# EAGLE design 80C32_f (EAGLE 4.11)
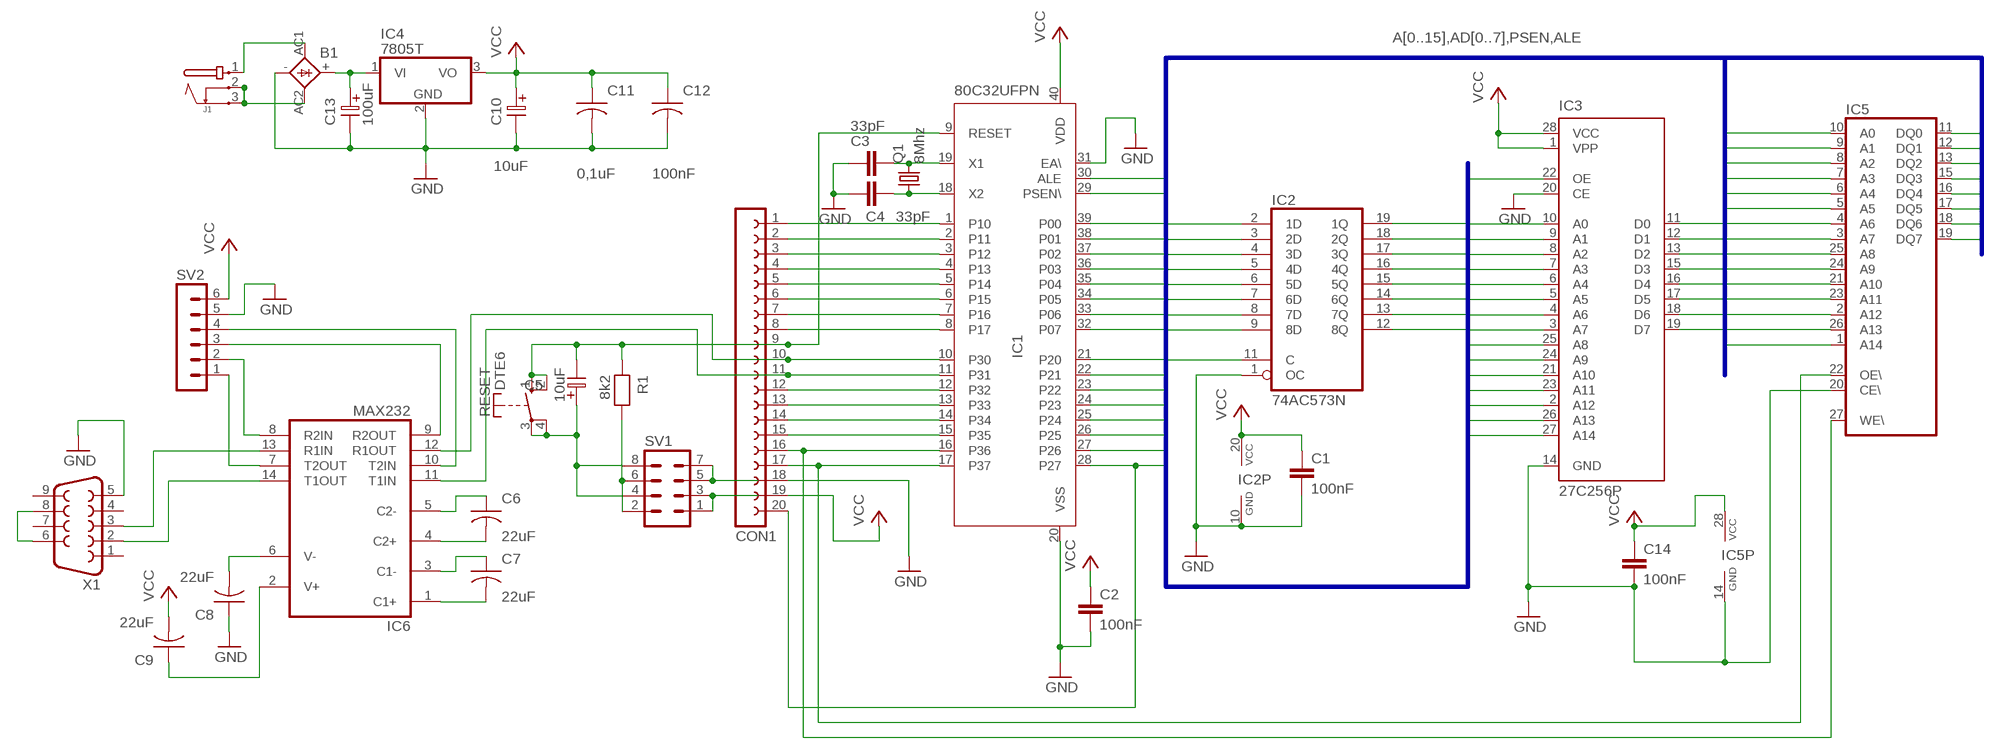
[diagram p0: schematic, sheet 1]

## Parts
B1  1KAB  [1KAB]
C1  100nF  C2,5-3  [C2.5-3]
C2  100nF  C2,5-3  [C2.5-3]
C3  33pF  C2,5-3  [C2.5-3]
C4  33pF  C2,5-3  [C2.5-3]
C5  10uF  ELC-5  [ES-5]
C6  22uF  CAP-2,5  [C-2,5]
C7  22uF  CAP-2,5  [C-2,5]
C8  22uF  CAP-2,5  [C-2,5]
C9  22uF  CAP-2,5  [C-2,5]
C10  10uF  ELC-5  [ES-5]
C11  0,1uF  CAP-5  [C-5]
C12  100nF  CAP-5  [C-5]
C13  100uF  ELC-5  [ES-5]
C14  100nF  C2,5-3  [C2.5-3]
CON1  FE20-1  [FE20]
IC1  80C32UFPN  [DIL40]
IC2  74AC573N  [DIL20]
IC3  27C256P  [DIL28-6]
IC4  7805T  [TO220H]
IC5  KM68257DIL28-3  [DIL28-3]
IC6  MAX232  [DIL16]
J1  JACK-PMS  [JACK-PMS]
Q1  8Mhz  HC49/S  [HC49/S]
R1  8k2  RESEU-5  [R-5]
RESET  DTE6  [DTE6]
SV1  MA04-2  [MA04-2]
SV2  MA06-1  [MA06-1]
X1  F09H  [F09H]

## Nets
A0: IC2.12(8Q) IC3.10(A0) IC5.10(A0)
A1: IC2.13(7Q) IC3.9(A1) IC5.9(A1)
A2: IC2.14(6Q) IC3.8(A2) IC5.8(A2)
A3: IC2.15(5Q) IC3.7(A3) IC5.7(A3)
A4: IC2.16(4Q) IC3.6(A4) IC5.6(A4)
A5: IC2.17(3Q) IC3.5(A5) IC5.5(A5)
A6: IC2.18(2Q) IC3.4(A6) IC5.4(A6)
A7: IC2.19(1Q) IC3.3(A7) IC5.3(A7)
A8: IC1.21(P20) IC3.25(A8) IC5.25(A8)
A9: IC1.22(P21) IC3.24(A9) IC5.24(A9)
A10: IC1.23(P22) IC3.21(A10) IC5.21(A10)
A11: IC1.24(P23) IC3.23(A11) IC5.23(A11)
A12: IC1.25(P24) IC3.2(A12) IC5.2(A12)
A13: IC1.26(P25) IC3.26(A13) IC5.26(A13)
A14: IC1.27(P26) IC3.27(A14) IC5.1(A14)
A15: CON1.20 IC1.28(P27)
AD0: IC1.39(P00) IC2.9(8D) IC3.11(D0) IC5.11(DQ0)
AD1: IC1.38(P01) IC2.8(7D) IC3.12(D1) IC5.12(DQ1)
AD2: IC1.37(P02) IC2.7(6D) IC3.13(D2) IC5.13(DQ2)
AD3: IC1.36(P03) IC2.6(5D) IC3.15(D3) IC5.15(DQ3)
AD4: IC1.35(P04) IC2.5(4D) IC3.16(D4) IC5.16(DQ4)
AD5: IC1.34(P05) IC2.4(3D) IC3.17(D5) IC5.17(DQ5)
AD6: IC1.33(P06) IC2.3(2D) IC3.18(D6) IC5.18(DQ6)
AD7: IC1.32(P07) IC2.2(1D) IC3.19(D7) IC5.19(DQ7)
ALE: IC1.30(ALE) IC2.11(C)
GND: B1.- C1.2 C2.2 C3.1 C4.1 C8.1 C10.2 C11.2 C12.2 C13.2 C14.2 CON1.18 IC1.20(VSS) IC1.31(EA\) IC2.1(OC) IC2.10(GND) IC3.14(GND) IC3.20(CE) IC4.2(GND) IC5.14(GND) IC5.20(CE\) SV1.5 SV1.7 SV2.5 X1.5
N$1: CON1.17 IC1.17(P37) IC5.22(OE\)
N$2: CON1.16 IC1.16(P36) IC5.27(WE\)
N$3: CON1.15 IC1.15(P35)
N$4: CON1.14 IC1.14(P34)
N$5: CON1.13 IC1.13(P33)
N$6: CON1.12 IC1.12(P32)
N$7: CON1.11 IC1.11(P31) IC6.11(T1IN)
N$8: CON1.10 IC1.10(P30) IC6.12(R1OUT)
N$9: CON1.8 IC1.8(P17)
N$10: CON1.7 IC1.7(P16)
N$11: CON1.6 IC1.6(P15)
N$12: CON1.5 IC1.5(P14)
N$13: CON1.4 IC1.4(P13)
N$14: CON1.3 IC1.3(P12)
N$15: CON1.2 IC1.2(P11)
N$16: CON1.1 IC1.1(P10)
N$17: C5.2 CON1.9 IC1.9(RESET) R1.1 RESET.1(S) RESET.2(S)
N$18: C4.2 IC1.18(X2) Q1.1
N$19: C3.2 IC1.19(X1) Q1.2
N$20: X1.6 X1.8
N$21: IC6.13(R1IN) X1.3
N$22: IC6.14(T1OUT) X1.2
N$23: IC6.7(T2OUT) SV2.1
N$24: IC6.8(R2IN) SV2.2
N$25: C9.1 IC6.2(V+)
N$26: C6.2 IC6.4(C2+)
N$27: C7.2 IC6.1(C1+)
N$28: C7.1 IC6.3(C1-)
N$29: C6.1 IC6.5(C2-)
N$30: C8.2 IC6.6(V-)
N$31: IC6.10(T2IN) SV2.4
N$32: IC6.9(R2OUT) SV2.3
N$33: B1.AC2 J1.2 J1.3
N$34: B1.AC1 J1.1
N$35: R1.2 SV1.2 SV1.6
N$36: B1.+ C13.1 IC4.1(VI)
N$37: C5.1 RESET.3(P) RESET.4(P) SV1.4 SV1.8
PSEN\: IC1.29(PSEN\) IC3.22(OE)
VCC: C1.1 C2.1 C9.2 C10.1 C11.1 C12.1 C14.1 CON1.19 IC1.40(VDD) IC2.20(VCC) IC3.1(VPP) IC3.28(VCC) IC4.3(VO) IC5.28(VCC) SV1.1 SV1.3 SV2.6
Unconnected: X1.1 X1.4 X1.7 X1.9

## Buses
A[0..15],AD[0..7],PSEN\,ALE

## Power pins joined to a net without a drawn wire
GND: IC6.15(GND)
VCC: IC6.16(VCC)

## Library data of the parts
B1 = rectifier:1KAB: RECTIFIER grid 5,08 x 5,08 mm
C1-C4 C14 = capacitor-wima:C: CAPACITOR
C5 C10 C13 = discrete:ELC-5
C6-C9 = discrete:CAP-2,5
C11 C12 = discrete:CAP-5
CON1 = con-lsta:FE20-1: FEMALE HEADER
IC1 = micro-philips:8*: CMOS single-chip 8-bit Microcontroller 80C31/32 pin compatible
IC2 = 74xx-eu:74*573: 8-bit D latch BUS DRIVER
IC3 = microchip:27*256: CMOS EPROM 256 K (32 K x 8), low voltage
IC4 = linear:78*: Positive VOLTAGE REGULATOR
IC5 = memory-samsung:KM68257: MEMORY
IC6 = maxim:MAX232: RS232 TRANSEIVER
J1 = POWER-IN:JACK-PMS
Q1 = Crystal3:HC49/S: CRYSTAL
R1 = discrete:RESEU-5
RESET = switch-misc:DT: ITT SWITCH
SV1 = con-lstb:MA04-2: PIN HEADER
SV2 = con-lstb:MA06-1: PIN HEADER
X1 = con-subd:F09: HARTING SUB-D

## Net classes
1 Supply: width 1.016 mm, drill 24 mm, clearance 0.61 mm

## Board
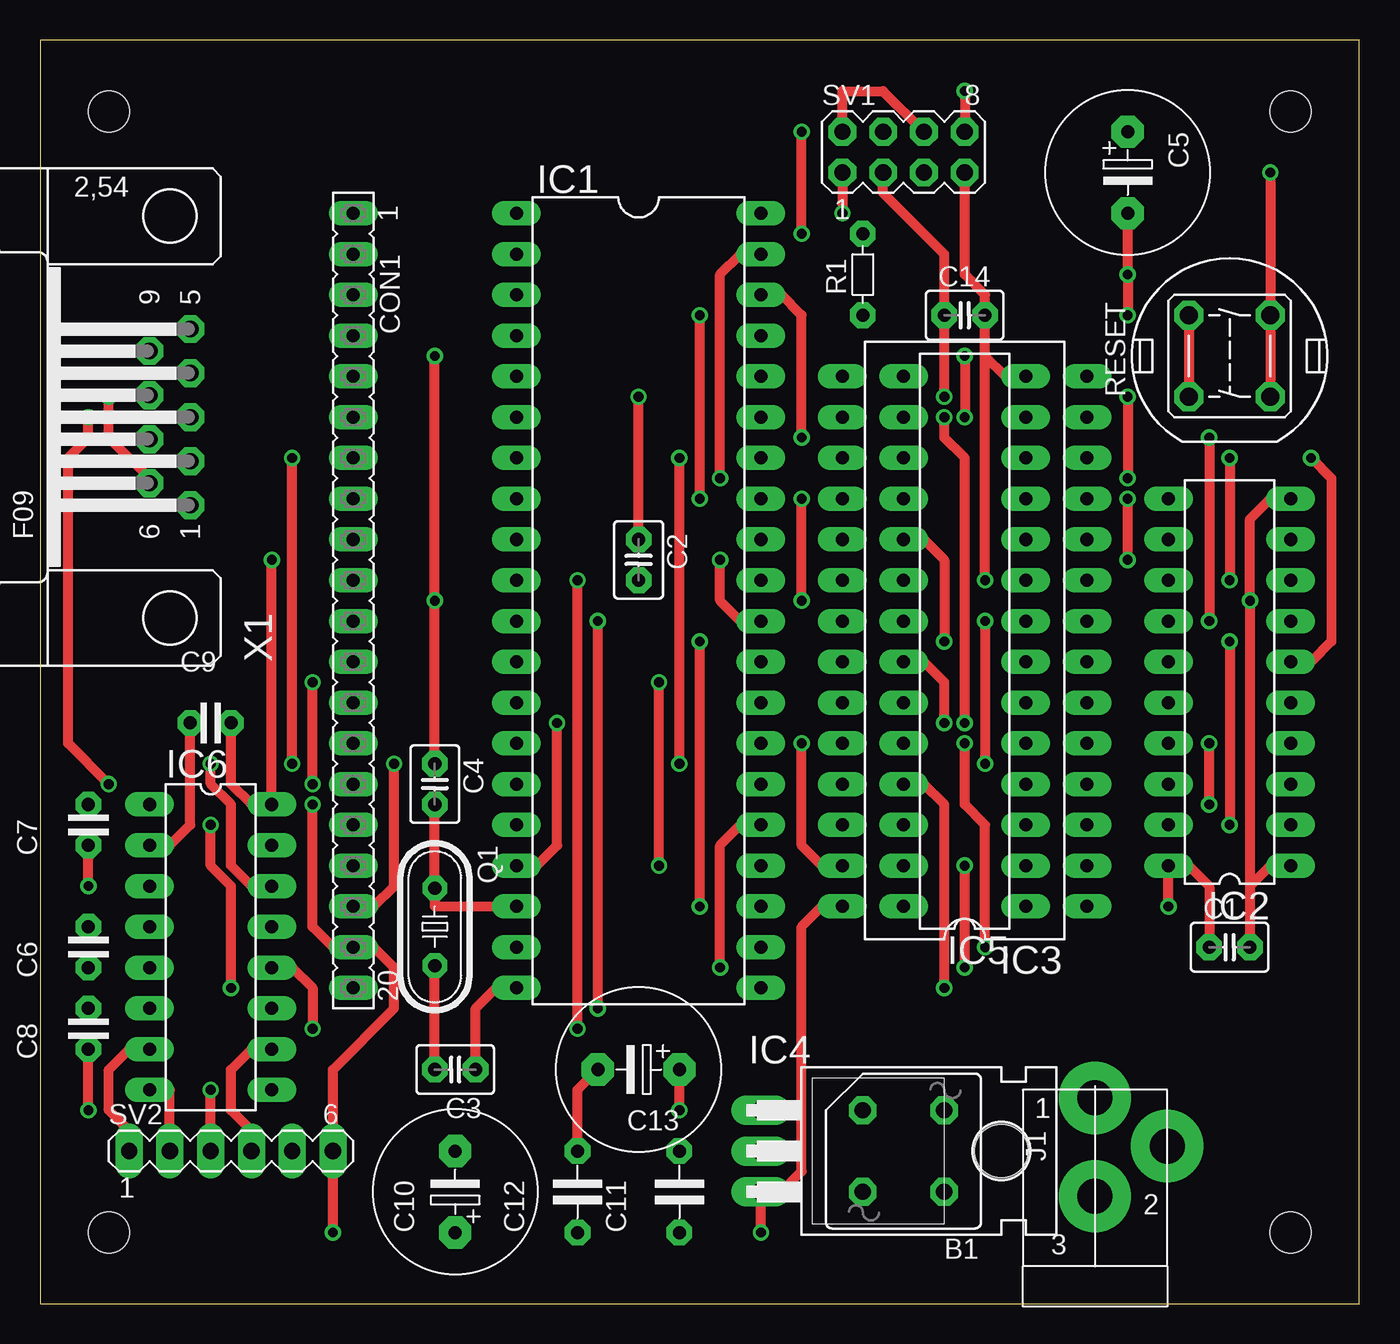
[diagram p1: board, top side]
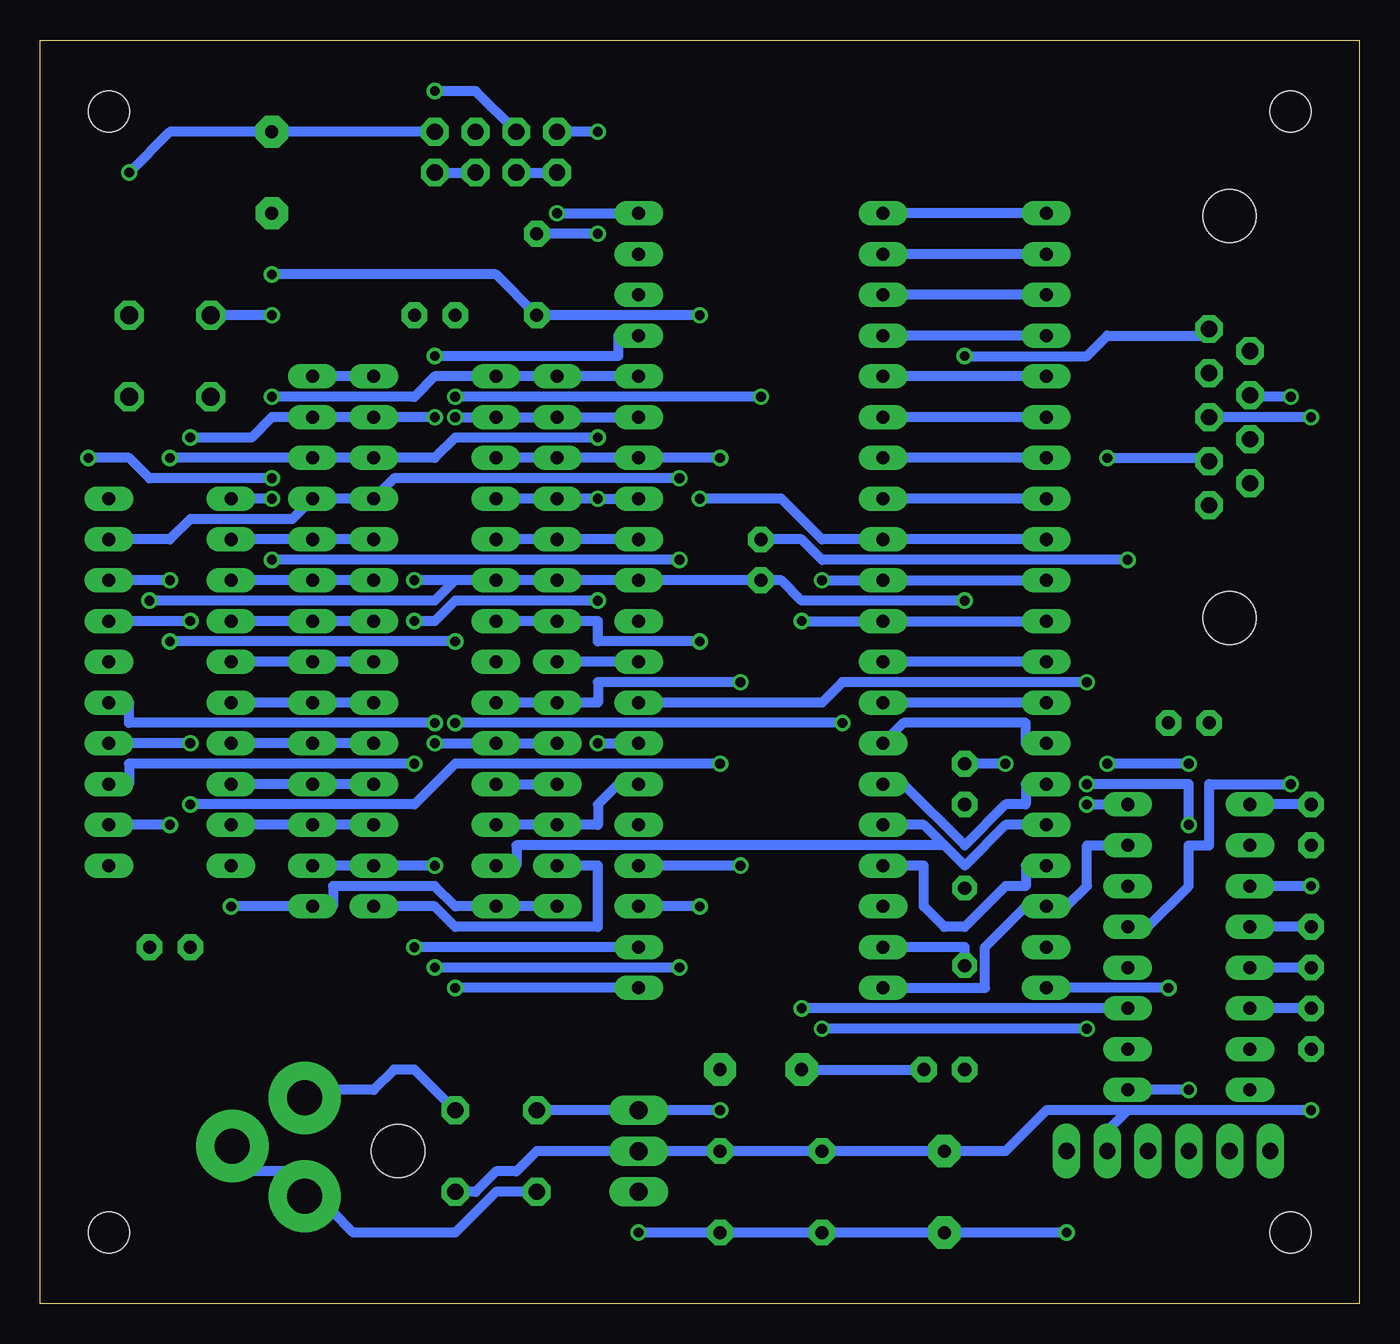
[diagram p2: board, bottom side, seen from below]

Size 82.22 x 78.73 mm. Coordinates in mm from the lower left corner, seen from the top.
Outline: 0,0 82.22,0 82.22,78.73 0,78.73 0,0
Copper layers (1*16): Top 0.035mm / dielectric 1.5mm / Bottom 0.035mm
Design rules "default": minimum track width 24mil, minimum drill 24mil, track to track 8mil, track to pad 8mil, pad to pad 8mil, via to via 8mil, smd to smd 8mil, copper to edge 40mil, drill to drill 8mil, minimum pad ring 14mil, minimum via ring 8mil, stop-mask expansion 4mil, vias tented up to drill 0mil, thermal gap 10mil
Holes 2.54 mm at 4.28,74.29 77.94,74.29 77.94,4.44 4.28,4.44

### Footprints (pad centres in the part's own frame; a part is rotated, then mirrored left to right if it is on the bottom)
1KAB = drill 1.016 octagon: + 2.54,-2.54; - -2.54,2.54; AC1 -2.54,-2.54; AC2 2.54,2.54
C2.5-3 = drill 0.813 pad 1.6 octagon: 1 -1.27,0; 2 1.27,0
ES-5 = drill 0.813 pad 2.007 octagon: 1 -2.54,0; 2 2.54,0
C-2,5 = drill 0.813 pad 1.6 octagon: 1 -1.27,0; 2 1.27,0
C-5 = drill 0.813 pad 1.6 octagon: 1 -2.54,0; 2 2.54,0
FE20 = drill 0.813 long: 1 -24.13,0; 2 -21.59,0; 3 -19.05,0; 4 -16.51,0; 5 -13.97,0; 6 -11.43,0; 7 -8.89,0; 8 -6.35,0; 9 -3.81,0; 10 -1.27,0; 11 1.27,0; 12 3.81,0; 13 6.35,0; 14 8.89,0; 15 11.43,0; 16 13.97,0; 17 16.51,0; 18 19.05,0; 19 21.59,0; 20 24.13,0
DIL40 = drill 0.813 long: 1 -24.13,-7.62; 2 -21.59,-7.62; 3 -19.05,-7.62; 4 -16.51,-7.62; 5 -13.97,-7.62; 6 -11.43,-7.62; 7 -8.89,-7.62; 8 -6.35,-7.62; 9 -3.81,-7.62; 10 -1.27,-7.62; 11 1.27,-7.62; 12 3.81,-7.62; 13 6.35,-7.62; 14 8.89,-7.62; 15 11.43,-7.62; 16 13.97,-7.62; 17 16.51,-7.62; 18 19.05,-7.62; 19 21.59,-7.62; 20 24.13,-7.62; 21 24.13,7.62; 22 21.59,7.62; 23 19.05,7.62; 24 16.51,7.62; 25 13.97,7.62; 26 11.43,7.62; 27 8.89,7.62; 28 6.35,7.62; 29 3.81,7.62; 30 1.27,7.62; 31 -1.27,7.62; 32 -3.81,7.62; 33 -6.35,7.62; 34 -8.89,7.62; 35 -11.43,7.62; 36 -13.97,7.62; 37 -16.51,7.62; 38 -19.05,7.62; 39 -21.59,7.62; 40 -24.13,7.62
DIL20 = drill 0.813 long: 1 -11.43,-3.81; 2 -8.89,-3.81; 3 -6.35,-3.81; 4 -3.81,-3.81; 5 -1.27,-3.81; 6 1.27,-3.81; 7 3.81,-3.81; 8 6.35,-3.81; 9 8.89,-3.81; 10 11.43,-3.81; 11 11.43,3.81; 12 8.89,3.81; 13 6.35,3.81; 14 3.81,3.81; 15 1.27,3.81; 16 -1.27,3.81; 17 -3.81,3.81; 18 -6.35,3.81; 19 -8.89,3.81; 20 -11.43,3.81
DIL28-6 = drill 0.813 long: 1 -16.51,-7.62; 2 -13.97,-7.62; 3 -11.43,-7.62; 4 -8.89,-7.62; 5 -6.35,-7.62; 6 -3.81,-7.62; 7 -1.27,-7.62; 8 1.27,-7.62; 9 3.81,-7.62; 10 6.35,-7.62; 11 8.89,-7.62; 12 11.43,-7.62; 13 13.97,-7.62; 14 16.51,-7.62; 15 16.51,7.62; 16 13.97,7.62; 17 11.43,7.62; 18 8.89,7.62; 19 6.35,7.62; 20 3.81,7.62; 21 1.27,7.62; 22 -1.27,7.62; 23 -3.81,7.62; 24 -6.35,7.62; 25 -8.89,7.62; 26 -11.43,7.62; 27 -13.97,7.62; 28 -16.51,7.62
TO220H = drill 1.118 long: 1 -2.54,-10.16; 2 0,-10.16; 3 2.54,-10.16 | hole 3.302: 0,4.826
DIL28-3 = drill 0.813 long: 1 -16.51,-3.81; 2 -13.97,-3.81; 3 -11.43,-3.81; 4 -8.89,-3.81; 5 -6.35,-3.81; 6 -3.81,-3.81; 7 -1.27,-3.81; 8 1.27,-3.81; 9 3.81,-3.81; 10 6.35,-3.81; 11 8.89,-3.81; 12 11.43,-3.81; 13 13.97,-3.81; 14 16.51,-3.81; 15 16.51,3.81; 16 13.97,3.81; 17 11.43,3.81; 18 8.89,3.81; 19 6.35,3.81; 20 3.81,3.81; 21 1.27,3.81; 22 -1.27,3.81; 23 -3.81,3.81; 24 -6.35,3.81; 25 -8.89,3.81; 26 -11.43,3.81; 27 -13.97,3.81; 28 -16.51,3.81
DIL16 = drill 0.813 long: 1 -8.89,-3.81; 2 -6.35,-3.81; 3 -3.81,-3.81; 4 -1.27,-3.81; 5 1.27,-3.81; 6 3.81,-3.81; 7 6.35,-3.81; 8 8.89,-3.81; 9 8.89,3.81; 10 6.35,3.81; 11 3.81,3.81; 12 1.27,3.81; 13 -1.27,3.81; 14 -3.81,3.81; 15 -6.35,3.81; 16 -8.89,3.81
JACK-PMS = drill 2.184 pad 4.5 round: 1 -0.5,-3.31; 2 -5,-0.31; 3 -0.5,2.809
HC49/S = drill 0.813 octagon: 1 -2.413,0; 2 2.413,0
R-5 = drill 0.813 pad 1.6 octagon: 1 -2.54,0; 2 2.54,0
DTE6 = drill 1.118 octagon: 1 -2.54,2.54; 2 2.54,2.54; 3 2.54,-2.54; 4 -2.54,-2.54
MA04-2 = drill 1.016 octagon: 1 -3.81,-1.27; 2 -3.81,1.27; 3 -1.27,-1.27; 4 -1.27,1.27; 5 1.27,-1.27; 6 1.27,1.27; 7 3.81,-1.27; 8 3.81,1.27
MA06-1 = drill 1.016 long: 1 -6.35,0; 2 -3.81,0; 3 -1.27,0; 4 1.27,0; 5 3.81,0; 6 6.35,0
F09H = drill 1.016 octagon: 1 -5.486,-1.27; 2 -2.743,-1.27; 3 0,-1.27; 4 2.743,-1.27; 5 5.486,-1.27; 6 -4.115,1.27; 7 -1.372,1.27; 8 1.372,1.27; 9 4.115,1.27 | hole 3.302: -12.522,0; 12.522,0

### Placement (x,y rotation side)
B1  53.81,9.52 180 top
C1  74.13,22.22 0 top
C2  37.3,46.35 270 top
C3  25.87,14.6 180 top
C4  24.6,32.38 270 top
C5  67.78,70.48 270 top
C6  3.01,22.22 90 top
C7  3.01,29.84 90 top
C8  3.01,17.14 90 top
C9  10.63,36.19 0 top
C10  25.87,6.98 90 top
C11  39.84,6.98 90 top
C12  33.49,6.98 90 top
C13  37.3,14.6 180 top
C14  57.62,61.59 0 top
CON1  19.52,43.81 270 top
IC1  37.3,43.81 270 top
IC2  74.13,38.73 90 top
IC3  57.62,41.27 90 top
IC4  55.08,9.52 270 top
IC5  57.62,41.27 90 top
IC6  10.63,22.22 270 top
J1  65.24,9.52 180 top
Q1  24.6,23.49 270 top
R1  51.27,64.13 90 top
RESET  74.13,59.05 90 top
SV1  53.81,71.75 0 top
SV2  11.9,9.52 0 top
X1  8.09,55.24 90 top

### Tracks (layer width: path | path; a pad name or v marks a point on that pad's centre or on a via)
A0
  Bottom 0.61: IC5.10 IC3.10 IC2.12
A1
  Bottom 0.61: IC5.9 IC3.9 IC2.13
A2
  Bottom 0.61: IC5.8 IC3.8 IC2.14
A3
  Bottom 0.61: IC5.7 IC3.7 IC2.15
A4
  Bottom 0.61: IC5.6 IC3.6 IC2.16
A5
  Bottom 0.61: IC5.5 IC3.5 IC2.17
A6
  Bottom 0.61: IC5.4 IC3.4 IC2.18
A7
  Bottom 0.61: IC5.3 IC3.3 IC2.19
A8  (via drill 0.61)
  Top 0.61: v56.35,19.68 56.35,31.11 55.08,32.38 IC5.25
  Bottom 0.61: IC1.21 v56.35,19.68 | IC5.25 IC3.25
A9  (via drill 0.61)
  Top 0.61: v58.89,22.22 58.89,29.84 57.62,31.11 v57.62,34.92
  Bottom 0.61: IC1.22 v58.89,22.22 | v57.62,34.92 IC5.24 IC3.24
A10  (via drill 0.61)
  Top 0.61: v41.11,24.76 v41.11,41.27
  Bottom 0.61: v41.11,41.27 47.46,41.27 47.46,42.54 IC3.21 IC5.21 | v41.11,24.76 IC1.23
A11  (via drill 0.61)
  Top 0.61: v38.57,27.3 v38.57,38.73
  Bottom 0.61: v38.57,38.73 47.46,38.73 47.46,37.46 IC3.23 IC5.23 | v38.57,27.3 IC1.24
A12  (via drill 0.61)
  Top 0.61: v42.38,20.95 42.38,28.57 43.65,29.84 IC1.25 | v57.62,20.95 v57.62,27.3
  Bottom 0.61: IC3.2 IC5.2 v57.62,27.3 | v42.38,20.95 v57.62,20.95
A13
  Bottom 0.61: IC5.26 IC3.26 47.46,29.84 47.46,31.11 46.19,32.38 IC1.26
A14  (via drill 0.61)
  Top 0.61: v47.46,34.92 47.46,28.57 48.73,27.3 IC3.27
  Bottom 0.61: v47.46,34.92 IC1.27 | IC5.1 57.62,24.76 56.35,23.49 47.46,23.49 47.46,27.3 IC3.27
A15  (via drill 0.61)
  Top 0.61: v11.9,19.68 11.9,26.03 10.63,27.3 v10.63,29.84 | v16.98,32.38 v16.98,38.73
  Bottom 0.61: v10.63,29.84 10.63,32.38 v16.98,32.38 | v16.98,38.73 32.22,38.73 33.49,37.46 IC1.28 | v11.9,19.68 CON1.20
AD0  (via drill 0.61)
  Top 0.61: v42.38,51.43 42.38,64.13 43.65,65.4 IC1.39
  Bottom 0.61: v42.38,51.43 60.16,51.43 IC5.11 IC3.11 66.51,48.89 72.86,48.89 74.13,47.62 IC2.9
AD1  (via drill 0.61)
  Top 0.61: v47.46,53.97 47.46,61.59 46.19,62.86 IC1.38 | v74.13,52.7 v74.13,45.08
  Bottom 0.61: v47.46,53.97 56.35,53.97 57.62,52.7 IC5.12 IC3.12 v74.13,52.7 | v74.13,45.08 IC2.8
AD2  (via drill 0.61)
  Top 0.61: v57.62,59.05 v57.62,55.24 | v72.86,53.97 v72.86,42.54
  Bottom 0.61: v57.62,59.05 46.19,59.05 46.19,60.32 IC1.37 | v57.62,55.24 IC5.13 IC3.13 67.78,55.24 69.05,53.97 v72.86,53.97 | v72.86,42.54 IC2.7
AD3  (via drill 0.61)
  Top 0.61: v79.21,52.7 80.48,51.43 80.48,41.27 79.21,40 IC2.6 | v67.78,56.51 v67.78,51.43
  Bottom 0.61: IC1.36 IC3.15 IC5.15 57.62,57.78 58.89,56.51 v67.78,56.51 | v79.21,52.7 76.67,52.7 75.4,51.43 v67.78,51.43
AD4  (via drill 0.61)
  Top 0.61: v57.62,36.19 57.62,52.7 56.35,53.97 v56.35,55.24
  Bottom 0.61: IC1.35 IC3.16 IC5.16 v56.35,55.24 | v57.62,36.19 76.67,36.19 76.67,37.46 IC2.5
AD5  (via drill 0.61)
  Top 0.61: v72.86,31.11 v72.86,34.92 | v39.84,33.65 v39.84,52.7
  Bottom 0.61: IC5.17 IC3.17 IC1.34 v39.84,52.7 | v72.86,31.11 58.89,31.11 56.35,33.65 v39.84,33.65 | v72.86,34.92 IC2.4
AD6  (via drill 0.61)
  Top 0.61: v58.89,42.54 v58.89,33.65 | v47.46,43.81 v47.46,50.16
  Bottom 0.61: IC1.33 v47.46,50.16 IC3.18 IC5.18 | v58.89,33.65 76.67,33.65 76.67,32.38 IC2.3 | v58.89,42.54 57.62,42.54 56.35,43.81 v47.46,43.81
AD7  (via drill 0.61)
  Top 0.61: v74.13,41.27 v74.13,29.84 | v56.35,41.27 56.35,46.35 55.08,47.62 IC5.19
  Bottom 0.61: IC1.32 IC3.19 IC5.19 | v56.35,41.27 v74.13,41.27 | v74.13,29.84 IC2.2
ALE  (via drill 0.61)
  Top 0.61: v42.38,46.35 42.38,43.81 43.65,42.54 IC1.30 | v67.78,46.35 v67.78,50.16
  Bottom 0.61: v42.38,46.35 v67.78,46.35 | v67.78,50.16 IC2.11
GND  (via drill 0.61)
  Top 0.61: C3.1 27.14,18.41 28.41,19.68 IC1.20 | v3.01,12.06 C8.1 | C13.2 33.49,13.33 C12.2 | 75.4,26.03 76.67,27.3 IC2.1 | 75.4,26.03 C1.2 | 75.4,26.03 v75.4,43.81 75.4,48.89 76.67,50.16 IC2.10 | 58.89,59.05 C14.2 58.89,62.86 57.62,64.13 SV1.7 | 58.89,59.05 60.16,57.78 IC5.14 | C4.1 v24.6,43.81 v24.6,59.05 | v58.89,45.08 58.89,59.05 | v22.06,33.65 22.06,26.03 20.79,24.76 CON1.18
  Bottom 0.61: IC6.15 16.98,28.57 16.98,26.03 18.25,24.76 CON1.18 20.79,24.76 23.33,22.22 23.33,19.68 IC1.20 | C13.2 C3.1 | v3.01,12.06 14.44,12.06 | 14.44,12.06 15.71,10.79 SV2.5 | B1.- 55.08,6.98 53.81,8.25 52.54,8.25 51.27,9.52 IC4.2 C11.2 C12.2 C10.2 22.06,9.52 19.52,12.06 14.44,12.06 | SV1.7 SV1.5 | IC5.14 IC3.14 | v24.6,43.81 34.76,43.81 36.03,45.08 C2.2 IC1.31 IC3.20 IC5.20 56.35,45.08 | v24.6,59.05 16.98,59.05 15.71,60.32 9.36,60.32 X1.5 | 56.35,45.08 v58.89,45.08 | v75.4,43.81 57.62,43.81 56.35,45.08 | v22.06,33.65 C4.1
N$1  (via drill 0.61)
  Top 0.61: v56.35,36.19 56.35,38.73 55.08,40 IC5.22 | v32.22,36.19 32.22,28.57 30.95,27.3 IC1.17
  Bottom 0.61: CON1.17 20.79,27.3 20.79,26.03 22.06,26.03 24.6,23.49 25.87,23.49 27.14,24.76 27.14,27.3 IC1.17 | v32.22,36.19 v56.35,36.19
N$2
  Bottom 0.61: 25.87,28.57 27.14,29.84 IC1.16 | 25.87,28.57 24.6,27.3 22.06,29.84 CON1.16 | 25.87,28.57 52.54,28.57 52.54,27.3 IC5.27
N$3
  Bottom 0.61: CON1.15 20.79,32.38 20.79,31.11 22.06,31.11 24.6,28.57 28.41,32.38 IC1.15
N$4
  Bottom 0.61: IC1.14 28.41,36.19 20.79,36.19 20.79,34.92 CON1.14
N$5
  Bottom 0.61: CON1.13 IC1.13
N$6
  Bottom 0.61: CON1.12 IC1.12
N$7  (via drill 0.61)
  Top 0.61: v34.76,18.41 v34.76,42.54
  Bottom 0.61: IC6.11 v34.76,18.41 | v34.76,42.54 IC1.11 CON1.11
N$8  (via drill 0.61)
  Top 0.61: v16.98,17.14 16.98,19.68 15.71,20.95 IC6.12 | v33.49,17.14 v33.49,45.08
  Bottom 0.61: v16.98,17.14 v33.49,17.14 | v33.49,45.08 IC1.10 CON1.10
N$9
  Bottom 0.61: CON1.8 IC1.8
N$10
  Bottom 0.61: CON1.7 IC1.7
N$11
  Bottom 0.61: CON1.6 IC1.6
N$12
  Bottom 0.61: CON1.5 IC1.5
N$13
  Bottom 0.61: CON1.4 IC1.4
N$14
  Bottom 0.61: CON1.3 IC1.3
N$15
  Bottom 0.61: CON1.2 IC1.2
N$16
  Bottom 0.61: CON1.1 IC1.1
N$17  (via drill 0.61)
  Top 0.61: RESET.2 RESET.1 | C5.2 v67.78,64.13 v67.78,61.59 | v41.11,50.16 v41.11,61.59
  Bottom 0.61: CON1.9 IC1.9 33.49,47.62 36.03,50.16 v41.11,50.16 | v67.78,64.13 53.81,64.13 R1.1 v41.11,61.59 | v67.78,61.59 RESET.2
N$18
  Top 0.61: IC1.18 24.6,24.76 Q1.1 24.6,26.03 C4.2
N$19
  Top 0.61: C3.2 Q1.2
  Bottom 0.61: IC1.19 24.6,22.22 Q1.2 24.6,20.95
N$20  (via drill 0.61)
  Top 0.61: v4.28,56.51 4.28,53.97 6.82,51.43 X1.6
  Bottom 0.61: v4.28,56.51 6.82,56.51 X1.8
N$21  (via drill 0.61)
  Top 0.61: v4.28,32.38 1.74,34.92 1.74,52.7 3.01,53.97 v3.01,55.24
  Bottom 0.61: v4.28,32.38 9.36,32.38 9.36,28.57 10.63,28.57 10.63,26.03 13.17,23.49 IC6.13 | v3.01,55.24 X1.3
N$22  (via drill 0.61)
  Top 0.61: v10.63,33.65 10.63,32.38 11.9,31.11 11.9,27.3 13.17,26.03 IC6.14 | v15.71,33.65 v15.71,52.7
  Bottom 0.61: v10.63,33.65 v15.71,33.65 | v15.71,52.7 9.36,52.7 X1.2
N$23
  Top 0.61: IC6.7 5.55,15.87 4.28,14.6 4.28,12.06 5.55,10.79 SV2.1
N$24
  Top 0.61: IC6.8 8.09,13.33 SV2.2
N$25
  Top 0.61: C9.1 9.36,29.84 8.09,28.57 IC6.2
N$26
  Bottom 0.61: C6.2 IC6.4
N$27
  Bottom 0.61: C7.2 IC6.1
N$28  (via drill 0.61)
  Top 0.61: v3.01,26.03 C7.1
  Bottom 0.61: v3.01,26.03 IC6.3
N$29
  Bottom 0.61: C6.1 IC6.5
N$30
  Bottom 0.61: C8.2 IC6.6
N$31
  Top 0.61: IC6.10 13.17,15.87 11.9,14.6 11.9,12.06 13.17,10.79 SV2.4
N$32  (via drill 0.61)
  Top 0.61: SV2.3 v10.63,13.33
  Bottom 0.61: v10.63,13.33 IC6.9
N$33
  Bottom 0.61: B1.AC2 53.81,6.98 56.35,4.44 62.7,4.44 63.97,5.71 J1.3 66.51,8.25 69.05,8.25 J1.2
N$34
  Bottom 0.61: B1.AC1 58.89,14.6 60.16,14.6 61.43,13.33 63.97,13.33 J1.1
N$35  (via drill 0.61)
  Top 0.61: v47.46,66.67 v47.46,73.02 | SV1.6 52.54,75.56 50,75.56 SV1.2
  Bottom 0.61: v47.46,66.67 R1.2 | v47.46,73.02 SV1.2
N$36  (via drill 0.61)
  Top 0.61: v39.84,12.06 C13.1
  Bottom 0.61: B1.+ IC4.1 v39.84,12.06
N$37  (via drill 0.61)
  Top 0.61: RESET.4 RESET.3 v76.67,70.48 | v57.62,75.56 SV1.8
  Bottom 0.61: SV1.4 55.08,75.56 v57.62,75.56 | SV1.8 C5.1 74.13,73.02 v76.67,70.48
PSEN\
  Bottom 0.61: IC1.29 IC3.22
VCC  (via drill 0.61)
  Top 0.61: C1.1 72.86,26.03 71.59,27.3 IC2.20 v70.32,24.76 | v18.25,4.44 SV2.6 18.25,14.6 22.06,18.41 22.06,20.95 20.79,22.22 CON1.19 18.25,22.22 16.98,23.49 v16.98,31.11 | v44.92,4.44 IC4.3 46.19,6.98 47.46,8.25 47.46,23.49 48.73,24.76 IC3.28 | SV1.1 v50,67.94 | SV1.3 52.54,69.21 56.35,65.4 C14.1 v56.35,56.51 | C9.2 11.9,32.38 13.17,31.11 IC6.16 v14.44,46.35 | C2.1 v37.3,56.51
  Bottom 0.61: IC3.28 IC5.28 56.35,24.76 57.62,26.03 63.97,26.03 63.97,24.76 IC3.1 v70.32,24.76 | v18.25,4.44 C10.1 C12.1 C11.1 v44.92,4.44 | v50,67.94 IC1.40 | SV1.3 SV1.1 | v16.98,31.11 IC6.16 | C2.1 34.76,47.62 33.49,46.35 v14.44,46.35 | v37.3,56.51 v56.35,56.51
